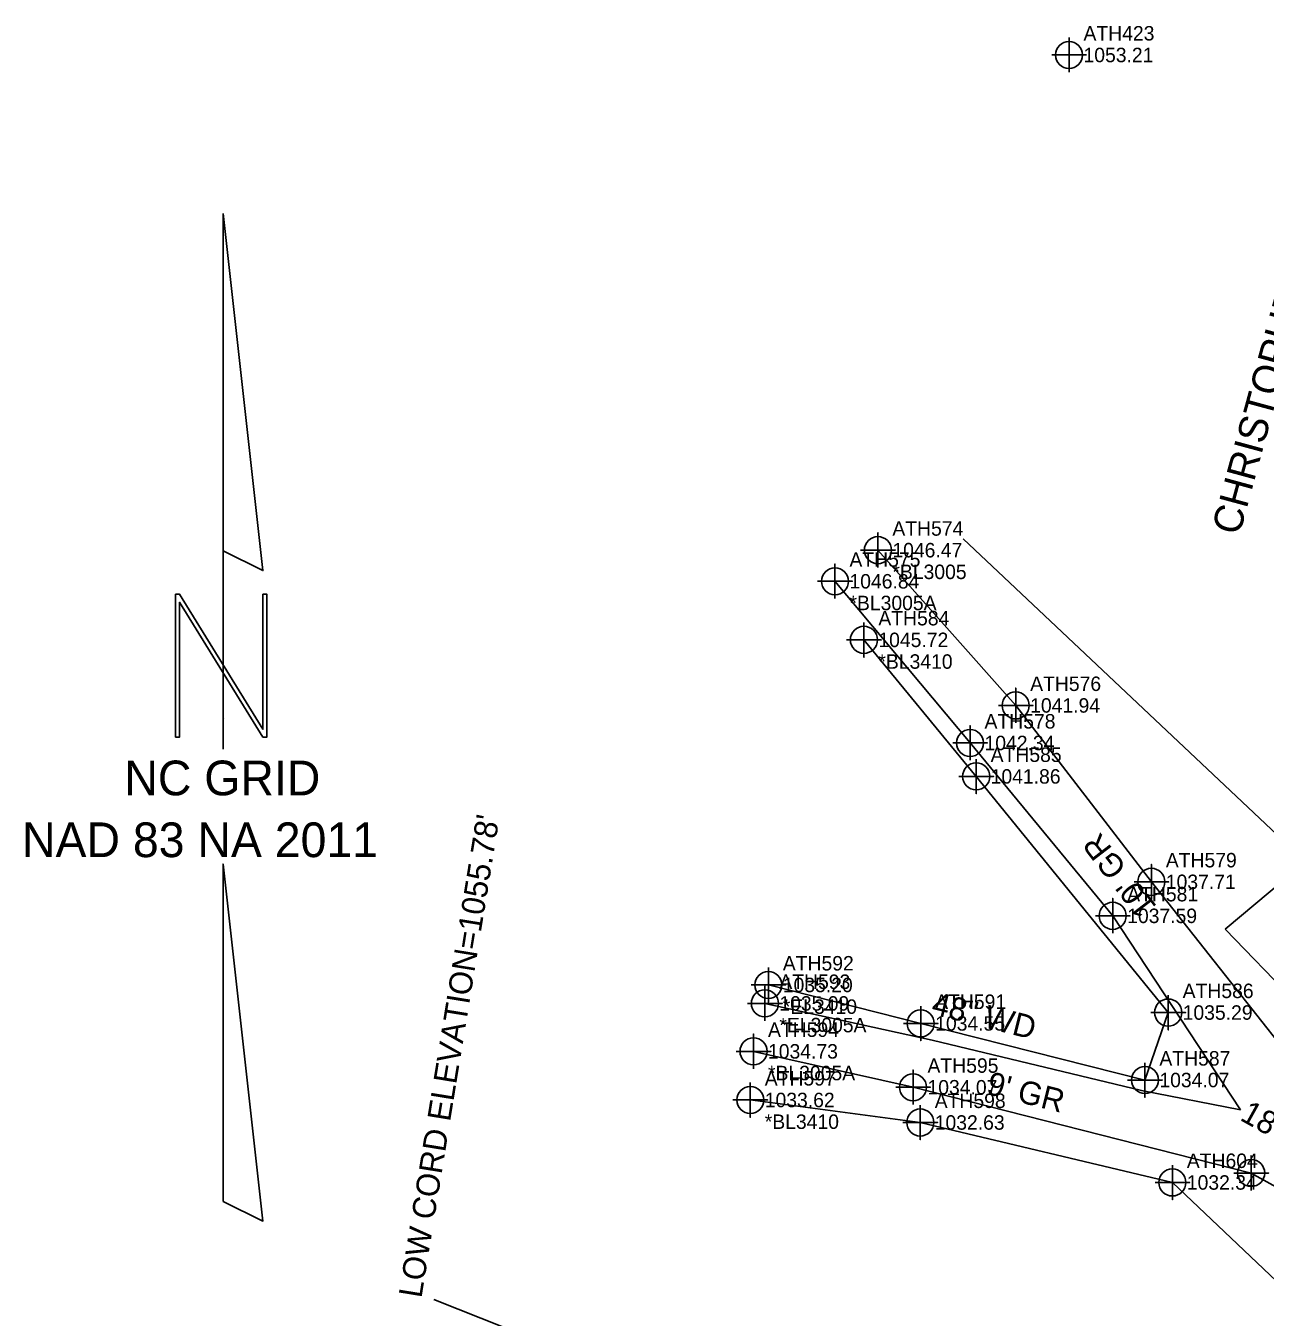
# Model space of a CAD drawing. Extents: x 1212084 to 1214478, y 765637 to 767408.
# Drawn here: x 1213108.1 to 1213322.3, y 766583.1 to 766806.4 of the extents above; entities that cross this region are included whole.
import ezdxf

# ---------------------------------------------------------------- set-up
doc = ezdxf.new("R2010")
doc.units = 0
for name, color, linetype in [('Cogo Default Point CELL', 7, 'Continuous'), ('COGO Default Point Elevation', 7, 'Continuous'), ('COGO Default Point Number', 7, 'Continuous'), ('CTL North Arrow NAD 83 NA 2011 CELL', 7, 'Continuous'), ('Exist Other Culture Fence Line', 7, 'Continuous'), ('Exist Other Culture Fence Line Cogo Comment', 7, 'Continuous'), ('Exist Other Culture Fence Line Cogo Elevation', 7, 'Continuous'), ('Exist Other Culture Fence Line Cogo Number', 7, 'Continuous'), ('Exist Other Culture Fence Line Cogo Point CELL', 7, 'Continuous'), ('Exist Other Culture Fence Line Text', 7, 'Continuous'), ('Exist Property Owner Text', 7, 'Continuous'), ('Exist Roads Soil', 7, 'Continuous'), ('Exist Roads Soil Cogo Comment', 7, 'Continuous'), ('Exist Roads Soil Cogo Elevation', 7, 'Continuous'), ('Exist Roads Soil Cogo Number', 7, 'Continuous'), ('Exist Roads Soil Cogo Point CELL', 7, 'Continuous'), ('Exist Roads Soil Text', 7, 'Continuous'), ('Exist Utilities Other Located Object Text', 7, 'Continuous'), ('Exist Vegetation Woods Line', 7, 'Continuous')]:
    doc.layers.add(name, color=color, linetype=linetype)

msp = doc.modelspace()

# ---------------------------------------------------------------- linework, layer by layer
at = {"layer": 'Cogo Default Point CELL'}
for points in [[(1213288.42, 766804.32), (1213288.42, 766801.32)], [(1213285.42, 766801.32), (1213288.42, 766801.32)], [(1213288.42, 766801.32), (1213291.42, 766801.32)], [(1213288.42, 766801.32), (1213288.42, 766798.32)]]:
    msp.add_lwpolyline(points, dxfattribs=at)
msp.add_circle((1213288.42, 766801.32), 2.34, dxfattribs=at)
at = {"layer": 'CTL North Arrow NAD 83 NA 2011 CELL'}
msp.add_line((1213142.34, 766686.64), (1213142.34, 766686.64), dxfattribs=at)
for points in [[(1213142.19, 766773.93), (1213142.19, 766715.6), (1213149.07, 766712.17)], [(1213133.97, 766683.38), (1213134.65, 766683.38), (1213134.65, 766706.7), (1213149.07, 766683.38), (1213149.75, 766683.38), (1213149.75, 766708.07), (1213149.07, 766708.07), (1213149.07, 766684.74), (1213134.65, 766708.07), (1213133.97, 766708.07)], [(1213142.19, 766603.09), (1213149.07, 766599.68), (1213142.19, 766661.42)]]:
    msp.add_lwpolyline(points, close=True, dxfattribs=at)
msp.add_lwpolyline([(1213142.19, 766715.6), (1213142.19, 766681.3)], dxfattribs=at)
at = {"layer": 'Exist Other Culture Fence Line'}
msp.add_line((1213338.12, 766653.48), (1213270.13, 766717.65), dxfattribs=at)
for points in [[(1213252.96, 766700.19), (1213272.37, 766676.58), (1213305.56, 766635.75), (1213301.54, 766624.08), (1213262.78, 766633.87), (1213236.44, 766640.52)], [(1213233.32, 766620.63), (1213262.7, 766616.74), (1213306.28, 766606.37), (1213326.51, 766587.15), (1213300.79, 766523.95)]]:
    msp.add_lwpolyline(points, dxfattribs=at)
at = {"layer": 'Exist Other Culture Fence Line Cogo Point CELL'}
for points in [[(1213252.96, 766703.19), (1213252.96, 766697.19), (1213252.96, 766700.19), (1213255.96, 766700.19), (1213249.96, 766700.19)], [(1213272.37, 766679.58), (1213272.37, 766673.58), (1213272.37, 766676.58), (1213275.37, 766676.58), (1213269.37, 766676.58)], [(1213236.44, 766643.52), (1213236.44, 766637.52), (1213236.44, 766640.52), (1213239.44, 766640.52), (1213233.44, 766640.52)], [(1213305.56, 766638.75), (1213305.56, 766632.75), (1213305.56, 766635.75), (1213308.56, 766635.75), (1213302.56, 766635.75)], [(1213262.78, 766636.87), (1213262.78, 766630.87), (1213262.78, 766633.87), (1213265.78, 766633.87), (1213259.78, 766633.87)], [(1213301.54, 766627.08), (1213301.54, 766621.08), (1213301.54, 766624.08), (1213304.54, 766624.08), (1213298.54, 766624.08)], [(1213233.32, 766623.63), (1213233.32, 766617.63), (1213233.32, 766620.63), (1213236.32, 766620.63), (1213230.32, 766620.63)], [(1213262.7, 766619.74), (1213262.7, 766613.74), (1213262.7, 766616.74), (1213265.7, 766616.74), (1213259.7, 766616.74)], [(1213306.28, 766609.37), (1213306.28, 766603.37), (1213306.28, 766606.37), (1213309.28, 766606.37), (1213303.28, 766606.37)]]:
    msp.add_lwpolyline(points, dxfattribs=at)
for centre in [(1213252.96, 766700.19), (1213272.37, 766676.58), (1213236.44, 766640.52), (1213305.56, 766635.75), (1213262.78, 766633.87), (1213301.54, 766624.08), (1213233.32, 766620.63), (1213262.7, 766616.74), (1213306.28, 766606.37)]:
    msp.add_circle(centre, 2.34, dxfattribs=at)
at = {"layer": 'Exist Roads Soil'}
for points in [[(1213255.38, 766715.7), (1213279.2, 766688.85), (1213302.65, 766658.35), (1213330, 766623.78), (1213351.82, 766609.27)], [(1213247.96, 766710.32), (1213271.31, 766682.36), (1213295.97, 766652.47), (1213318.05, 766618.91)], [(1213318.05, 766618.91), (1213300.95, 766622.28), (1213264.73, 766630.95), (1213235.84, 766637.33)], [(1213233.88, 766629.04), (1213261.45, 766622.83), (1213319.9, 766608), (1213347.58, 766592.63)]]:
    msp.add_lwpolyline(points, dxfattribs=at)
at = {"layer": 'Exist Roads Soil Cogo Point CELL'}
for points in [[(1213255.38, 766712.7), (1213255.38, 766718.7), (1213255.38, 766715.7), (1213258.38, 766715.7), (1213252.38, 766715.7)], [(1213247.96, 766707.32), (1213247.96, 766713.32), (1213247.96, 766710.32), (1213250.96, 766710.32), (1213244.96, 766710.32)], [(1213279.2, 766685.85), (1213279.2, 766691.85), (1213279.2, 766688.85), (1213282.2, 766688.85), (1213276.2, 766688.85)], [(1213271.31, 766679.36), (1213271.31, 766685.36), (1213271.31, 766682.36), (1213274.31, 766682.36), (1213268.31, 766682.36)], [(1213302.65, 766655.35), (1213302.65, 766661.35), (1213302.65, 766658.35), (1213305.65, 766658.35), (1213299.65, 766658.35)], [(1213295.97, 766649.47), (1213295.97, 766655.47), (1213295.97, 766652.47), (1213298.97, 766652.47), (1213292.97, 766652.47)], [(1213235.84, 766634.33), (1213235.84, 766640.33), (1213235.84, 766637.33), (1213238.84, 766637.33), (1213232.84, 766637.33)], [(1213233.88, 766626.04), (1213233.88, 766632.04), (1213233.88, 766629.04), (1213236.88, 766629.04), (1213230.88, 766629.04)], [(1213261.45, 766619.83), (1213261.45, 766625.83), (1213261.45, 766622.83), (1213264.45, 766622.83), (1213258.45, 766622.83)], [(1213319.9, 766605), (1213319.9, 766611), (1213319.9, 766608), (1213322.9, 766608), (1213316.9, 766608)]]:
    msp.add_lwpolyline(points, dxfattribs=at)
for centre in [(1213255.38, 766715.7), (1213247.96, 766710.32), (1213279.2, 766688.85), (1213271.31, 766682.36), (1213302.65, 766658.35), (1213295.97, 766652.47), (1213235.84, 766637.33), (1213233.88, 766629.04), (1213261.45, 766622.83), (1213319.9, 766608)]:
    msp.add_circle(centre, 2.34, dxfattribs=at)
at = {"layer": 'Exist Utilities Other Located Object Text'}
msp.add_line((1213309.29, 766534.31), (1213178.62, 766586.15), dxfattribs=at)
at = {"layer": 'Exist Vegetation Woods Line'}
msp.add_lwpolyline([(1213315.42, 766650.17), (1213336.29, 766667.62), (1213359.45, 766657.83), (1213357.82, 766642.01), (1213350.32, 766625.37), (1213342.16, 766624.39), (1213339.06, 766625.7), (1213315.42, 766650.17)], dxfattribs=at)

# ---------------------------------------------------------------- texts
at = {"layer": 'COGO Default Point Elevation'}
msp.add_text('1053.21', height=2.5, dxfattribs=at).set_placement((1213290.92, 766800.07))
at = {"layer": 'COGO Default Point Number'}
msp.add_text('ATH423', height=2.5, dxfattribs=at).set_placement((1213290.92, 766803.82))
at = {"layer": 'CTL North Arrow NAD 83 NA 2011 CELL'}
for s, p in [('NC GRID', (1213125.11, 766673.31)), ('NAD 83 NA 2011', (1213107.42, 766662.62))]:
    msp.add_text(s, height=6, dxfattribs=at).set_placement(p)
at = {"layer": 'Exist Other Culture Fence Line Cogo Comment'}
for s, p in [('*BL3410', (1213255.46, 766695.19)), ('*EL3410', (1213238.94, 766635.52)), ('*BL3410', (1213235.82, 766615.63))]:
    msp.add_text(s, height=2.5, dxfattribs=at).set_placement(p)
at = {"layer": 'Exist Other Culture Fence Line Cogo Elevation'}
for s, p in [('1045.72', (1213255.46, 766698.94)), ('1041.86', (1213274.87, 766675.33)), ('1035.20', (1213238.94, 766639.27)), ('1035.29', (1213308.06, 766634.5)), ('1034.55', (1213265.28, 766632.62)), ('1034.07', (1213304.04, 766622.83)), ('1033.62', (1213235.82, 766619.38)), ('1032.63', (1213265.2, 766615.49)), ('1032.34', (1213308.78, 766605.12))]:
    msp.add_text(s, height=2.5, dxfattribs=at).set_placement(p)
at = {"layer": 'Exist Other Culture Fence Line Cogo Number'}
for s, p in [('ATH584', (1213255.46, 766702.69)), ('ATH585', (1213274.87, 766679.08)), ('ATH592', (1213238.94, 766643.02)), ('ATH586', (1213308.06, 766638.25)), ('ATH591', (1213265.28, 766636.37)), ('ATH587', (1213304.04, 766626.58)), ('ATH597', (1213235.82, 766623.13)), ('ATH598', (1213265.2, 766619.24)), ('ATH604', (1213308.78, 766608.87))]:
    msp.add_text(s, height=2.5, dxfattribs=at).set_placement(p)
at = {"layer": 'Exist Other Culture Fence Line Text'}
msp.add_text('48" WD', height=4, rotation=345.8265, dxfattribs=at).set_placement((1213264.42, 766635.52))
at = {"layer": 'Exist Property Owner Text'}
msp.add_text('CHRISTOPHER CARLOCK', height=5, rotation=74.7888, dxfattribs=at).set_placement((1213317.85, 766718.09))
at = {"layer": 'Exist Roads Soil Cogo Comment'}
for s, p in [('*BL3005', (1213257.88, 766710.7)), ('*BL3005A', (1213250.46, 766705.32)), ('*EL3005A', (1213238.34, 766632.33)), ('*BL3005A', (1213236.38, 766624.04))]:
    msp.add_text(s, height=2.5, dxfattribs=at).set_placement(p)
at = {"layer": 'Exist Roads Soil Cogo Elevation'}
for s, p in [('1046.47', (1213257.88, 766714.45)), ('1046.84', (1213250.46, 766709.07)), ('1041.94', (1213281.7, 766687.6)), ('1042.34', (1213273.81, 766681.11)), ('1037.71', (1213305.15, 766657.1)), ('1037.59', (1213298.47, 766651.22)), ('1035.09', (1213238.34, 766636.08)), ('1034.73', (1213236.38, 766627.79)), ('1034.07', (1213263.95, 766621.58))]:
    msp.add_text(s, height=2.5, dxfattribs=at).set_placement(p)
at = {"layer": 'Exist Roads Soil Cogo Number'}
for s, p in [('ATH574', (1213257.88, 766718.2)), ('ATH575', (1213250.46, 766712.82)), ('ATH576', (1213281.7, 766691.35)), ('ATH578', (1213273.81, 766684.86)), ('ATH579', (1213305.15, 766660.85)), ('ATH581', (1213298.47, 766654.97)), ('ATH593', (1213238.34, 766639.83)), ('ATH594', (1213236.38, 766631.54)), ('ATH595', (1213263.95, 766625.33))]:
    msp.add_text(s, height=2.5, dxfattribs=at).set_placement(p)
at = {"layer": 'Exist Roads Soil Text'}
for s, rotation, p in [("10' GR", 127.5647, (1213303.7, 766654.06)), ("9' GR", 345.7686, (1213273.95, 766621.72)), ("18' GRAVEL", 330.9478, (1213317.77, 766617.25))]:
    msp.add_text(s, height=4, rotation=rotation, dxfattribs=at).set_placement(p)
at = {"layer": 'Exist Utilities Other Located Object Text'}
msp.add_text("LOW CORD ELEVATION=1055.78'", height=4, rotation=80.7739, dxfattribs=at).set_placement((1213176.46, 766586.27))

doc.saveas('drawing.dxf')
